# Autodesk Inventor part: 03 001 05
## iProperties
Shininess: 64.0
Length Units: 11269
Angle Units: 11279
Time Units: 11290
Mass Units: 11283
Length Display Precision: 3
Angle Display Precision: 2
Compacted: True
Part Number: 03 001 05
Document SubType Name: Modeling
Created: 2003-12
Material: Standard
Designer: HAH
Manufacturer: Standard
Standards Organization: Custom
Description: Dach
Density: 0.0
Volumn: 0.0
Area: 0.0
PropertySet Name: Model Information
Control State: 0
Master: False
Checked Out: False
Author: HAH
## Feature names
1. Extrusion1
